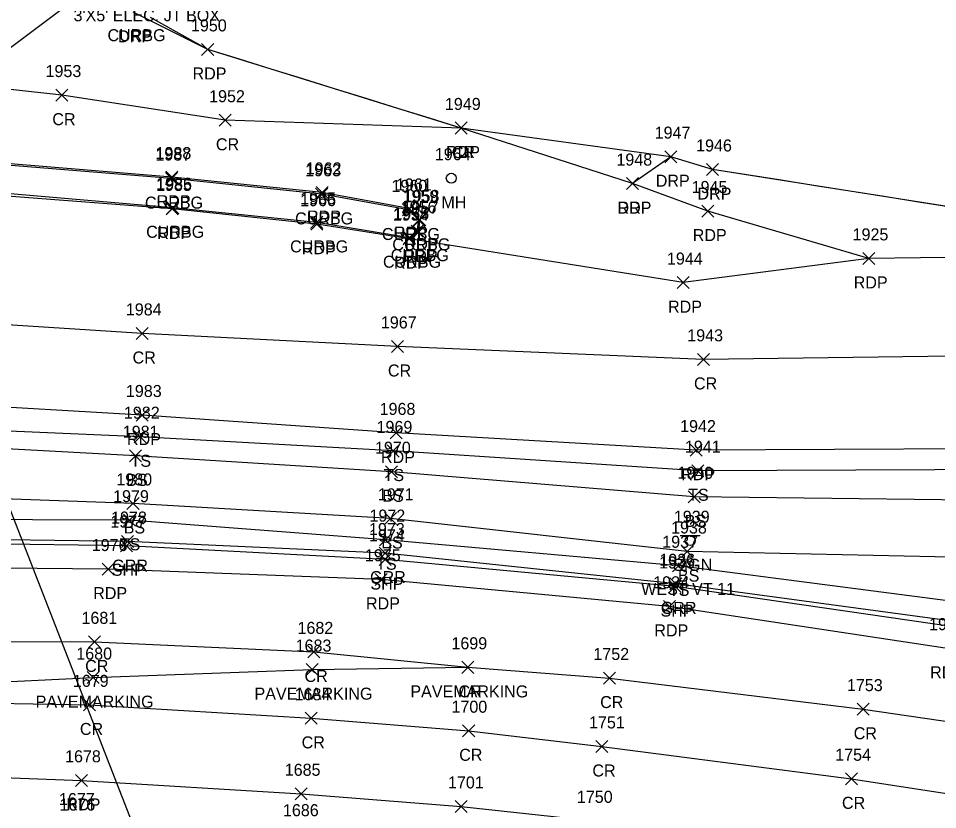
# Model space of a CAD drawing. Extents: x 49137 to 50946, y 9590 to 10709.
# Drawn here: x 50341.4 to 50494.3, y 10054.9 to 10186.5 of the extents above; entities that cross this region are included whole.
import ezdxf

# ---------------------------------------------------------------- set-up
doc = ezdxf.new("R2010")
doc.units = 0
for name, color, linetype in [('DCP', 7, 'Continuous'), ('L_A', 7, 'Continuous'), ('L_I', 7, 'Continuous'), ('L_TIC', 7, 'Continuous'), ('LELB', 7, 'Continuous'), ('LSOGP', 7, 'Continuous'), ('P_A', 7, 'Continuous'), ('P_I', 7, 'Continuous'), ('P_TIC', 7, 'Continuous'), ('PET', 7, 'Continuous'), ('PRC', 7, 'Continuous'), ('PSP', 7, 'Continuous'), ('R_A', 7, 'Continuous'), ('R_I', 7, 'Continuous'), ('R_TIC', 7, 'Continuous'), ('RC', 7, 'Continuous'), ('RDP', 7, 'Continuous'), ('RGR', 7, 'Continuous'), ('S_A', 7, 'Continuous'), ('S_C', 7, 'Continuous'), ('S_I', 7, 'Continuous'), ('S_TIC', 7, 'Continuous'), ('SSGN', 7, 'Continuous'), ('STS', 7, 'Continuous'), ('U_A', 7, 'Continuous'), ('U_C', 7, 'Continuous'), ('U_I', 7, 'Continuous'), ('UUMH', 7, 'Continuous')]:
    doc.layers.add(name, color=color, linetype=linetype)

msp = doc.modelspace()

# ---------------------------------------------------------------- linework, layer by layer
at = {"layer": 'DCP'}
msp.add_lwpolyline([(49941.69, 9827.48), (50059.34, 9808.37), (50181.4, 9733.09), (50281.74, 9743.29), (50422.72, 9892.52), (50122.34, 10663.61), (50179.93, 10552.61), (50179.64, 10394.45), (50122.34, 10285.07), (50121.56, 10284.35)], dxfattribs=at)
at = {"layer": 'L_TIC'}
for points in [[(50360.62, 10115.94), (50362.62, 10117.94)], [(50362.62, 10115.94), (50360.62, 10117.94)], [(50402.7, 10113.57), (50404.7, 10115.57)], [(50404.7, 10113.57), (50402.7, 10115.57)], [(50359.87, 10112.77), (50361.87, 10114.77)], [(50361.87, 10112.77), (50359.87, 10114.77)], [(50402.46, 10110.12), (50404.46, 10112.12)], [(50404.46, 10110.12), (50402.46, 10112.12)], [(50453.37, 10110.29), (50455.37, 10112.29)], [(50455.37, 10110.29), (50453.37, 10112.29)], [(50452.77, 10105.95), (50454.77, 10107.95)], [(50454.77, 10105.95), (50452.77, 10107.95)], [(50359.44, 10104.85), (50361.44, 10106.85)], [(50361.44, 10104.85), (50359.44, 10106.85)], [(50358.84, 10102.05), (50360.84, 10104.05)], [(50360.84, 10102.05), (50358.84, 10104.05)], [(50402.29, 10102.36), (50404.29, 10104.36)], [(50404.29, 10102.36), (50402.29, 10104.36)], [(50401.46, 10098.82), (50403.46, 10100.82)], [(50403.46, 10098.82), (50401.46, 10100.82)], [(50451.63, 10096.84), (50453.63, 10098.84)], [(50453.63, 10096.84), (50451.63, 10098.84)], [(50450.16, 10094.47), (50452.16, 10096.47)], [(50452.16, 10094.47), (50450.16, 10096.47)]]:
    msp.add_lwpolyline(points, dxfattribs=at)
at = {"layer": 'LELB'}
for points in [[(50533.21, 10111.61), (50454.37, 10111.29), (50403.7, 10114.57), (50361.62, 10116.94), (50329.48, 10118.31), (50280.68, 10120.52), (50237.29, 10122.22), (50191.56, 10123.07), (50146.81, 10122.77), (50115.16, 10122.31), (50083.39, 10121.86), (50041.97, 10119), (50028.32, 10115.17), (50016.29, 10109.07), (50004.38, 10096.89), (49998.69, 10083.53), (49995.83, 10073.63), (49998.74, 10070.59), (50003.66, 10071.93), (50011.01, 10077.24), (50017.53, 10082.53), (50020.31, 10080.95)], [(50644.74, 10103.97), (50611.95, 10100.78), (50591.59, 10097.05), (50585.39, 10096.69), (50579.07, 10095.78), (50533.17, 10102.58), (50499.54, 10106.39), (50453.77, 10106.95), (50403.46, 10111.12), (50360.87, 10113.77), (50329.07, 10115.48), (50280.62, 10115.79), (50236.61, 10117.17), (50191.06, 10116.35), (50147.05, 10116.34), (50114.68, 10115.11), (50083.47, 10115.05), (50044.28, 10110), (50029.63, 10109.76), (50016.5, 10101.02), (50008.23, 10092.1), (50002.09, 10081.32)], [(50656.33, 10076.99), (50615.69, 10084.11), (50585.23, 10087.97), (50578.18, 10088.24), (50532.06, 10091.89), (50499.01, 10096.85), (50452.63, 10097.84), (50403.29, 10103.36), (50360.44, 10105.85), (50327.92, 10107.02), (50280.05, 10107.28), (50236.47, 10108.2), (50190.71, 10107.88), (50147.64, 10108.13), (50115.13, 10105.8), (50083.07, 10105.28), (50046.19, 10099.87), (50032.18, 10100.38), (50021.32, 10094.18), (50013.13, 10086.72), (50006.19, 10078.9), (50001.56, 10073.09), (49999.89, 10073.29), (50002.09, 10081.32)], [(50497.71, 10089.44), (50451.16, 10095.47), (50402.46, 10099.82), (50359.84, 10103.05), (50327.51, 10103.16), (50279.96, 10102.01), (50237.11, 10099.39), (50191.33, 10094.96), (50149.08, 10088.85)]]:
    msp.add_lwpolyline(points, dxfattribs=at)
at = {"layer": 'LSOGP'}
for points in [[(50353.86, 10192.03), (50331.98, 10175.56)], [(50496.81, 10155.08), (50491.1, 10155.98), (50485.39, 10156.88), (50479.68, 10157.78), (50473.97, 10158.68), (50468.26, 10159.59), (50462.56, 10160.49), (50456.85, 10161.39), (50449.9, 10163.52), (50415.02, 10168.29), (50409.75, 10169.92), (50404.48, 10171.56), (50399.21, 10173.19), (50393.94, 10174.82), (50388.67, 10176.46), (50383.4, 10178.09), (50378.13, 10179.73), (50372.86, 10181.36), (50368.11, 10184.03), (50363.36, 10186.69)]]:
    msp.add_lwpolyline(points, dxfattribs=at)
at = {"layer": 'P_TIC'}
for points in [[(50371.86, 10180.36), (50373.86, 10182.36)], [(50373.86, 10180.36), (50371.86, 10182.36)], [(50347.59, 10172.76), (50349.59, 10174.76)], [(50349.59, 10172.76), (50347.59, 10174.76)], [(50374.79, 10168.58), (50376.79, 10170.58)], [(50376.79, 10168.58), (50374.79, 10170.58)], [(50414.02, 10167.29), (50416.02, 10169.29)], [(50416.02, 10167.29), (50414.02, 10169.29)], [(50414.02, 10167.29), (50416.02, 10169.29)], [(50416.02, 10167.29), (50414.02, 10169.29)], [(50365.88, 10159.12), (50367.88, 10161.12)], [(50367.88, 10159.12), (50365.88, 10161.12)], [(50442.53, 10158.04), (50444.53, 10160.04)], [(50444.53, 10158.04), (50442.53, 10160.04)], [(50390.91, 10156.57), (50392.91, 10158.57)], [(50392.91, 10156.57), (50390.91, 10158.57)], [(50365.97, 10153.83), (50367.97, 10155.83)], [(50367.97, 10153.83), (50365.97, 10155.83)], [(50405.35, 10153.9), (50407.35, 10155.9)], [(50407.35, 10153.9), (50405.35, 10155.9)], [(50455.05, 10153.48), (50457.05, 10155.48)], [(50457.05, 10153.48), (50455.05, 10155.48)], [(50407.14, 10152), (50409.14, 10154)], [(50409.14, 10152), (50407.14, 10154)], [(50390.04, 10151.29), (50392.04, 10153.29)], [(50392.04, 10151.29), (50390.04, 10153.29)], [(50405.36, 10148.88), (50407.36, 10150.88)], [(50407.36, 10148.88), (50405.36, 10150.88)], [(50405.36, 10148.88), (50407.36, 10150.88)], [(50407.36, 10148.88), (50405.36, 10150.88)], [(50406.97, 10150.02), (50408.97, 10152.02)], [(50408.97, 10150.02), (50406.97, 10152.02)], [(50481.82, 10145.6), (50483.82, 10147.6)], [(50483.82, 10145.6), (50481.82, 10147.6)], [(50481.82, 10145.6), (50483.82, 10147.6)], [(50483.82, 10145.6), (50481.82, 10147.6)], [(50450.94, 10141.57), (50452.94, 10143.57)], [(50452.94, 10141.57), (50450.94, 10143.57)], [(50360.94, 10133.12), (50362.94, 10135.12)], [(50362.94, 10133.12), (50360.94, 10135.12)], [(50403.41, 10130.96), (50405.41, 10132.96)], [(50405.41, 10130.96), (50403.41, 10132.96)], [(50454.32, 10128.81), (50456.32, 10130.81)], [(50456.32, 10128.81), (50454.32, 10130.81)], [(50360.95, 10119.55), (50362.95, 10121.55)], [(50362.95, 10119.55), (50360.95, 10121.55)], [(50403.2, 10116.57), (50405.2, 10118.57)], [(50405.2, 10116.57), (50403.2, 10118.57)], [(50453.13, 10113.71), (50455.13, 10115.71)], [(50455.13, 10113.71), (50453.13, 10115.71)], [(50358.36, 10097.82), (50360.36, 10099.82)], [(50360.36, 10097.82), (50358.36, 10099.82)], [(50401.39, 10095.53), (50403.39, 10097.53)], [(50403.39, 10095.53), (50401.39, 10097.53)], [(50355.33, 10093.93), (50357.33, 10095.93)], [(50357.33, 10093.93), (50355.33, 10095.93)], [(50400.7, 10092.22), (50402.7, 10094.22)], [(50402.7, 10092.22), (50400.7, 10094.22)], [(50449.63, 10091.03), (50451.63, 10093.03)], [(50451.63, 10091.03), (50449.63, 10093.03)], [(50448.66, 10087.73), (50450.66, 10089.73)], [(50450.66, 10087.73), (50448.66, 10089.73)], [(50353.04, 10081.82), (50355.04, 10083.82)], [(50355.04, 10081.82), (50353.04, 10083.82)], [(50389.54, 10080.15), (50391.54, 10082.15)], [(50391.54, 10080.15), (50389.54, 10082.15)], [(50415.15, 10077.59), (50417.15, 10079.59)], [(50417.15, 10077.59), (50415.15, 10079.59)], [(50438.7, 10075.81), (50440.7, 10077.81)], [(50440.7, 10075.81), (50438.7, 10077.81)], [(50352.18, 10071.34), (50354.18, 10073.34)], [(50354.18, 10071.34), (50352.18, 10073.34)], [(50480.88, 10070.63), (50482.88, 10072.63)], [(50482.88, 10070.63), (50480.88, 10072.63)], [(50389.06, 10069.11), (50391.06, 10071.11)], [(50391.06, 10069.11), (50389.06, 10071.11)], [(50415.27, 10067.04), (50417.27, 10069.04)], [(50417.27, 10067.04), (50415.27, 10069.04)], [(50437.42, 10064.43), (50439.42, 10066.43)], [(50439.42, 10064.43), (50437.42, 10066.43)], [(50350.88, 10058.79), (50352.88, 10060.79)], [(50352.88, 10058.79), (50350.88, 10060.79)], [(50478.93, 10059.05), (50480.93, 10061.05)], [(50480.93, 10059.05), (50478.93, 10061.05)], [(50387.42, 10056.55), (50389.42, 10058.55)], [(50389.42, 10056.55), (50387.42, 10058.55)], [(50414.03, 10054.45), (50416.03, 10056.45)], [(50416.03, 10054.45), (50414.03, 10056.45)]]:
    msp.add_lwpolyline(points, dxfattribs=at)
at = {"layer": 'PET'}
for points in [[(50372.86, 10181.36), (50360.45, 10187.55)], [(50482.82, 10146.6), (50456.05, 10154.48), (50443.53, 10159.04), (50415.02, 10168.29), (50372.86, 10181.36)], [(50406.36, 10149.88), (50407.97, 10151.02), (50408.14, 10153), (50406.35, 10154.9), (50391.91, 10157.57), (50366.88, 10160.12), (50332.62, 10162.92), (50281.48, 10166.54), (50239.93, 10168.83), (50191.59, 10168.93), (50146.75, 10166.21), (50145.08, 10165.18), (50144.31, 10163.78), (50144.54, 10162.06), (50145.7, 10160.86), (50147.42, 10160.55)], [(50500, 10146.8), (50482.82, 10146.6), (50451.94, 10142.57), (50406.36, 10149.88), (50391.04, 10152.29), (50366.97, 10154.83), (50332.97, 10157.45), (50281.75, 10161.16), (50239.77, 10163.2), (50191.31, 10163.26), (50147.42, 10160.55), (50119.04, 10158.14), (50090.98, 10156.23), (50087.12, 10154.93), (50074.59, 10152.39), (50039.42, 10148.74), (50022.28, 10145.28), (50001.49, 10135.47), (49981.43, 10116.92), (49974.22, 10104.51), (49968.54, 10090.52), (49966.03, 10076.93), (49965.37, 10068.99)], [(50664.04, 10109.02), (50639.15, 10120.65), (50622.16, 10120.01), (50585.93, 10117.59), (50533.39, 10115.35), (50500.14, 10114.93), (50454.13, 10114.71), (50404.2, 10117.57), (50361.95, 10120.55), (50329.6, 10122.43), (50280.88, 10124.62), (50237.67, 10126.17), (50191.62, 10126.61), (50146.37, 10126.55), (50115.33, 10126.09), (50083.53, 10125.91), (50041.87, 10123.08), (50027.5, 10119.57), (50014.15, 10112.3), (50001.27, 10099.44), (49993.67, 10082.3), (49991.68, 10072.98), (49993.67, 10063.34)], [(50495.53, 10081.77), (50449.66, 10088.73), (50401.7, 10093.22), (50356.33, 10094.93), (50326.68, 10095.17), (50279.7, 10093.24), (50237.68, 10090.37), (50191.91, 10084.51), (50151.19, 10077.89), (50119.21, 10071.6), (50086.72, 10064.4), (50053.97, 10056.46), (50026.35, 10049.68), (49981.17, 10037.41), (49930.4, 10023.11), (49891.41, 10012.39), (49855.88, 10002.4), (49819.82, 9992.77), (49773.46, 9981.58), (49739, 9973.69)], [(49743.42, 9944.81), (49788.35, 9958.02), (49837.04, 9971.51), (49882.75, 9984.49), (49918.64, 9994.5), (49951.14, 10003.99), (49990.91, 10015.05), (50038.8, 10027.76), (50078.38, 10036.75), (50102.79, 10041.88), (50136.94, 10048.02), (50166.81, 10052.31), (50203.48, 10056.47), (50244.74, 10059.59), (50274.3, 10060.67), (50312.69, 10061.26), (50351.88, 10059.79), (50388.42, 10057.55), (50415.03, 10055.45), (50437.05, 10053.05), (50478.42, 10048.42), (50499.95, 10044.65)]]:
    msp.add_lwpolyline(points, dxfattribs=at)
at = {"layer": 'PRC'}
for points in [[(50415.02, 10168.29), (50375.79, 10169.58), (50348.59, 10173.76), (50331.98, 10175.57), (50281.35, 10178.48), (50239.93, 10181.21), (50190.51, 10181.45), (50142.28, 10178.74), (50127.58, 10174.55), (50105.38, 10173.38)], [(50496.82, 10130.36), (50455.32, 10129.81), (50404.41, 10131.96), (50361.94, 10134.12), (50331.7, 10136.07), (50280.64, 10137.31), (50238.72, 10140.09), (50190.79, 10138.96), (50146, 10140.16), (50115.75, 10139.22), (50082.65, 10138.75), (50040.31, 10135.56), (50024.84, 10132.27), (50007.81, 10123.3), (49990.28, 10107.59), (49982.88, 10090.76), (49978.98, 10075.39)], [(50106.74, 10055.97), (50133.96, 10061.74), (50166.12, 10067.98), (50201.45, 10073.89), (50243.79, 10078.94), (50274, 10081.14), (50312.1, 10082.96), (50354.04, 10082.82), (50390.54, 10081.15), (50416.15, 10078.59), (50439.7, 10076.81), (50481.88, 10071.63), (50505.07, 10068.26), (50535.23, 10062.54), (50570.45, 10054.93), (50608.05, 10045.74), (50637.59, 10037.1), (50673.65, 10027)], [(49741.53, 9956.86), (49785.57, 9969.42), (49835.05, 9983.34), (49879.41, 9996.17), (49916.09, 10006.01), (49947.12, 10015.1), (49988.02, 10026.32), (50036.19, 10039.26), (50070.37, 10047.79), (50106.74, 10055.97), (50134.51, 10059.88), (50166.08, 10064.33), (50202.42, 10068.7), (50244.36, 10071.5), (50274.74, 10072.55), (50312.43, 10073.1), (50353.18, 10072.34), (50390.06, 10070.11), (50416.27, 10068.04), (50438.42, 10065.43), (50479.93, 10060.05), (50503.35, 10056.42)]]:
    msp.add_lwpolyline(points, dxfattribs=at)
at = {"layer": 'PSP'}
msp.add_lwpolyline([(50496.83, 10085.32), (50450.63, 10092.03), (50402.39, 10096.53), (50359.36, 10098.82), (50327.14, 10099.23), (50280.12, 10097.78), (50237.97, 10094.88), (50191.64, 10089.51), (50150.54, 10083.69), (50117.84, 10077.88), (50085.62, 10071.48), (50052.95, 10063.95), (50024.27, 10056.62), (49980.23, 10044.39), (49928.03, 10029.66), (49890.75, 10019.13), (49853.57, 10008.09), (49830.16, 10002.15), (49807.71, 9999.09), (49769.91, 9990.82), (49738.16, 9982.81)], dxfattribs=at)
at = {"layer": 'R_TIC'}
for points in [[(50448.9, 10162.52), (50450.9, 10164.52)], [(50450.9, 10162.52), (50448.9, 10164.52)], [(50455.84, 10160.39), (50457.84, 10162.39)], [(50457.84, 10160.39), (50455.84, 10162.39)], [(50365.85, 10158.88), (50367.85, 10160.88)], [(50367.85, 10158.88), (50365.85, 10160.88)], [(50442.53, 10158.04), (50444.53, 10160.04)], [(50444.53, 10158.04), (50442.53, 10160.04)], [(50390.82, 10156.26), (50392.82, 10158.26)], [(50392.82, 10156.26), (50390.82, 10158.26)], [(50366.05, 10154.03), (50368.05, 10156.03)], [(50368.05, 10154.03), (50366.05, 10156.03)], [(50405.26, 10153.66), (50407.26, 10155.66)], [(50407.26, 10153.66), (50405.26, 10155.66)], [(50406.99, 10151.94), (50408.99, 10153.94)], [(50408.99, 10151.94), (50406.99, 10153.94)], [(50389.99, 10151.6), (50391.99, 10153.6)], [(50391.99, 10151.6), (50389.99, 10153.6)], [(50405.44, 10149.05), (50407.44, 10151.05)], [(50407.44, 10149.05), (50405.44, 10151.05)], [(50405.44, 10149.05), (50407.44, 10151.05)], [(50407.44, 10149.05), (50405.44, 10151.05)], [(50406.72, 10150.14), (50408.72, 10152.14)], [(50408.72, 10150.14), (50406.72, 10152.14)], [(50358.5, 10098.5), (50360.5, 10100.5)], [(50360.5, 10098.5), (50358.5, 10100.5)], [(50401.39, 10096.59), (50403.39, 10098.59)], [(50403.39, 10096.59), (50401.39, 10098.59)], [(50449.74, 10091.48), (50451.74, 10093.48)], [(50451.74, 10091.48), (50449.74, 10093.48)]]:
    msp.add_lwpolyline(points, dxfattribs=at)
at = {"layer": 'RC'}
for points in [[(50406.44, 10150.05), (50407.72, 10151.14), (50407.99, 10152.94), (50406.26, 10154.66), (50391.82, 10157.26), (50366.85, 10159.88), (50333.24, 10162.63), (50281.49, 10166.41), (50239.92, 10168.5), (50191.32, 10168.65), (50146.85, 10165.71), (50145.17, 10165.02), (50144.53, 10163.85), (50144.81, 10161.97), (50145.73, 10160.98), (50147.43, 10160.66)], [(50406.44, 10150.05), (50390.99, 10152.6), (50367.05, 10155.03), (50332.93, 10157.94), (50281.77, 10161.35), (50239.96, 10163.34), (50191.48, 10163.68), (50147.43, 10160.66)]]:
    msp.add_lwpolyline(points, dxfattribs=at)
at = {"layer": 'RDP'}
msp.add_lwpolyline([(50549.97, 10143.23), (50548.67, 10149.07), (50545.93, 10148.83), (50541.02, 10148.7), (50502.52, 10154.17), (50456.84, 10161.39), (50449.9, 10163.52), (50443.53, 10159.04)], dxfattribs=at)
at = {"layer": 'RGR'}
msp.add_lwpolyline([(50651.36, 10061.68), (50639.09, 10060.01), (50614.4, 10063.11), (50576.81, 10070.84), (50530.55, 10080.07), (50497.09, 10086.23), (50450.74, 10092.48), (50402.39, 10097.59), (50359.5, 10099.5), (50327.14, 10099.98), (50280.06, 10098.35), (50237.96, 10095.92), (50191.63, 10090.37), (50150.37, 10084.97), (50118.07, 10079.04), (50085.73, 10072.95), (50052.65, 10065.04), (50024.56, 10058.01), (49980.29, 10045.93), (49927.85, 10030.6), (49890.84, 10020.31), (49853.28, 10009.42), (49828.89, 10003.64), (49814.87, 10004.41)], dxfattribs=at)
at = {"layer": 'S_TIC'}
for points in [[(50389.23, 10077.21), (50391.23, 10079.21)], [(50391.23, 10077.21), (50389.23, 10079.21)], [(50415.15, 10077.59), (50417.15, 10079.59)], [(50417.15, 10077.59), (50415.15, 10079.59)], [(50352.83, 10075.88), (50354.83, 10077.88)], [(50354.83, 10075.88), (50352.83, 10077.88)]]:
    msp.add_lwpolyline(points, dxfattribs=at)
at = {"layer": 'SSGN'}
for p, q in [((50451.47, 10100.49), (50454.8, 10100.49)), ((50453.12, 10099.66), (50453.12, 10099.66))]:
    msp.add_line(p, q, dxfattribs=at)
msp.add_circle((50453.12, 10099.66), 0.833, dxfattribs=at)
at = {"layer": 'STS'}
msp.add_lwpolyline([(50274.74, 10072.55), (50312.62, 10074.9), (50353.83, 10076.88), (50390.23, 10078.21), (50416.15, 10078.59)], dxfattribs=at)
at = {"layer": 'UUMH'}
for p, q in [((50413.38, 10159.94), (50413.38, 10159.94)), ((50414.22, 10159.94), (50414.22, 10159.94))]:
    msp.add_line(p, q, dxfattribs=at)
msp.add_circle((50413.38, 10159.94), 0.833, dxfattribs=at)

# ---------------------------------------------------------------- texts
at = {"layer": 'L_A'}
for s, p in [('TS', (50360.03, 10111.94)), ('TS', (50402.11, 10109.57)), ('BS', (50359.31, 10108.77)), ('BS', (50401.91, 10106.12)), ('TS', (50452.78, 10106.29)), ('BS', (50452.21, 10101.95)), ('BS', (50358.89, 10100.85)), ('BS', (50401.73, 10098.36)), ('TS', (50358.24, 10098.05)), ('TS', (50400.87, 10094.82)), ('BS', (50451.07, 10092.84)), ('TS', (50449.57, 10090.47))]:
    msp.add_text(s, height=2, dxfattribs=at).set_placement(p)
at = {"layer": 'L_I'}
for s, p in [('1982', (50358.93, 10119.94)), ('1981', (50358.74, 10116.77)), ('1969', (50400.95, 10117.57)), ('1970', (50400.69, 10114.12)), ('1941', (50452.24, 10114.29)), ('1940', (50450.99, 10109.95)), ('1980', (50357.67, 10108.85)), ('1979', (50357.13, 10106.05)), ('1971', (50401.16, 10106.36)), ('1972', (50399.77, 10102.82)), ('1938', (50449.94, 10100.84)), ('1937', (50448.47, 10098.47))]:
    msp.add_text(s, height=2, dxfattribs=at).set_placement(p)
at = {"layer": 'P_A'}
for s, p in [('RDP', (50370.34, 10176.36)), ('CR', (50347.02, 10168.76)), ('CR', (50374.23, 10164.58)), ('RDP', (50412.51, 10163.29)), ('CR', (50413.46, 10163.29)), ('RDP', (50364.37, 10155.12)), ('RDP', (50441.02, 10154.04)), ('RDP', (50389.39, 10152.57)), ('RDP', (50364.46, 10149.83)), ('RDP', (50403.84, 10149.9)), ('RDP', (50453.54, 10149.48)), ('RDP', (50388.52, 10147.29)), ('RDP', (50405.63, 10148)), ('RDP', (50405.46, 10146.02)), ('RDP', (50403.84, 10144.88)), ('RDP', (50403.84, 10144.88)), ('RDP', (50480.31, 10141.6)), ('RDP', (50480.31, 10141.6)), ('RDP', (50449.43, 10137.57)), ('CR', (50360.37, 10129.12)), ('CR', (50402.84, 10126.96)), ('CR', (50453.75, 10124.81)), ('RDP', (50359.44, 10115.55)), ('RDP', (50401.69, 10112.57)), ('RDP', (50451.62, 10109.71)), ('SHP', (50356.9, 10093.82)), ('SHP', (50399.92, 10091.53)), ('RDP', (50353.82, 10089.93)), ('RDP', (50399.19, 10088.22)), ('SHP', (50448.17, 10087.03)), ('RDP', (50447.15, 10083.73)), ('CR', (50352.48, 10077.82)), ('CR', (50388.97, 10076.15)), ('RDP', (50493.02, 10076.77)), ('CR', (50414.58, 10073.59)), ('CR', (50438.14, 10071.81)), ('CR', (50351.61, 10067.34)), ('CR', (50480.31, 10066.63)), ('CR', (50388.49, 10065.11)), ('CR', (50414.7, 10063.04)), ('CR', (50436.85, 10060.43)), ('RDP', (50349.37, 10054.79)), ('CR', (50478.36, 10055.05))]:
    msp.add_text(s, height=2, dxfattribs=at).set_placement(p)
at = {"layer": 'P_I'}
for s, p in [('1950', (50370.08, 10184.36)), ('1953', (50345.89, 10176.76)), ('1952', (50373.1, 10172.58)), ('1949', (50412.32, 10171.29)), ('1949', (50412.32, 10171.29)), ('1988', (50364.19, 10163.12)), ('1948', (50440.84, 10162.04)), ('1962', (50389.17, 10160.57)), ('1985', (50364.27, 10157.83)), ('1961', (50404.17, 10157.9)), ('1945', (50453.36, 10157.48)), ('1966', (50388.24, 10155.29)), ('1958', (50405.45, 10156)), ('1957', (50405.28, 10154.02)), ('1954', (50403.66, 10152.88)), ('1954', (50403.66, 10152.88)), ('1925', (50480.13, 10149.6)), ('1925', (50480.13, 10149.6)), ('1944', (50449.25, 10145.57)), ('1984', (50359.25, 10137.12)), ('1967', (50401.67, 10134.96)), ('1943', (50452.63, 10132.81)), ('1983', (50359.26, 10123.55)), ('1968', (50401.46, 10120.57)), ('1942', (50451.44, 10117.71)), ('1977', (50356.67, 10101.82)), ('1974', (50399.69, 10099.53)), ('1976', (50353.58, 10097.93)), ('1975', (50399.01, 10096.22)), ('1935', (50447.94, 10095.03)), ('1934', (50446.97, 10091.73)), ('1681', (50351.87, 10085.82)), ('1933', (50492.84, 10084.77)), ('1682', (50387.8, 10084.15)), ('1699', (50413.4, 10081.59)), ('1752', (50437.01, 10079.81)), ('1679', (50350.43, 10075.34)), ('1753', (50479.19, 10074.63)), ('1684', (50387.32, 10073.11)), ('1700', (50413.41, 10071.04)), ('1751', (50436.29, 10068.43)), ('1754', (50477.24, 10063.05)), ('1678', (50349.14, 10062.79)), ('1685', (50385.68, 10060.55)), ('1701', (50412.83, 10058.45)), ('1677', (50348.12, 10055.67)), ('1750', (50434.27, 10056.05)), ('1686', (50385.38, 10053.83))]:
    msp.add_text(s, height=2, dxfattribs=at).set_placement(p)
at = {"layer": 'R_A'}
for s, p in [('CURBG', (50356.2, 10182.73)), ('DRP', (50357.94, 10182.55)), ('DRP', (50447.39, 10158.52)), ('DRP', (50454.33, 10156.39)), ('CURBG', (50362.43, 10154.88)), ('DRP', (50441.02, 10154.04)), ('CURBG', (50387.4, 10152.26)), ('CURBG', (50362.63, 10150.03)), ('CURBG', (50401.84, 10149.66)), ('CURBG', (50386.57, 10147.6)), ('CURBG', (50403.57, 10147.94)), ('CURBG', (50403.3, 10146.14)), ('CURBG', (50402.02, 10145.05)), ('CURBG', (50402.02, 10145.05)), ('GRR', (50356.99, 10094.5)), ('GRR', (50399.87, 10092.59)), ('GRR', (50448.23, 10087.48))]:
    msp.add_text(s, height=2, dxfattribs=at).set_placement(p)
at = {"layer": 'R_I'}
for s, p in [('1947', (50447.21, 10166.52)), ('1946', (50454.1, 10164.39)), ('1987', (50364.16, 10162.88)), ('1948', (50440.84, 10162.04)), ('1963', (50389.08, 10160.26)), ('1986', (50364.3, 10158.03)), ('1960', (50403.43, 10157.66)), ('1965', (50388.25, 10155.6)), ('1959', (50405.29, 10155.94)), ('1956', (50404.97, 10154.14)), ('1955', (50403.75, 10153.05)), ('1955', (50403.75, 10153.05)), ('1978', (50356.8, 10102.5)), ('1973', (50399.69, 10100.59)), ('1936', (50447.99, 10095.48)), ('1676', (50348.21, 10054.76))]:
    msp.add_text(s, height=2, dxfattribs=at).set_placement(p)
at = {"layer": 'S_A'}
for s, p in [('SIGN', (50450.25, 10094.64)), ('PAVEMARKING', (50380.65, 10073.21)), ('PAVEMARKING', (50406.57, 10073.59)), ('PAVEMARKING', (50344.25, 10071.88))]:
    msp.add_text(s, height=2, dxfattribs=at).set_placement(p)
at = {"layer": 'S_C'}
msp.add_text('WEST VT 11', height=2, dxfattribs=at).set_placement((50444.97, 10090.64))
at = {"layer": 'S_I'}
for s, p in [('1939', (50450.4, 10102.64)), ('1699', (50413.4, 10081.59)), ('1680', (50351.01, 10079.88)), ('1683', (50387.49, 10081.21))]:
    msp.add_text(s, height=2, dxfattribs=at).set_placement(p)
at = {"layer": 'U_A'}
msp.add_text('MH', height=2, dxfattribs=at).set_placement((50411.74, 10154.94))
at = {"layer": 'U_C'}
msp.add_text("3'X5' ELEC. JT BOX", height=2, dxfattribs=at).set_placement((50350.55, 10186.04))
at = {"layer": 'U_I'}
msp.add_text('1964', height=2, dxfattribs=at).set_placement((50410.64, 10162.94))

doc.saveas('drawing.dxf')
